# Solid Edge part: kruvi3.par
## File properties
Author: Mac
Template: Normal.par
Last saved by: Mac
Revision: 6
Application: Solid Edge
Material: Bronze, 90%
Face Style: Bronze
Fill Style: ANSI33(Brass)
Virtual Style: Brushed bronze
Coef. of Thermal Exp: 1.8e-05
Thermal Conductivity: 189.0
Specific Heat: 377.0
Modulus of Elasticity: 117210869000.0
Poission's Ratio: 0.36
Yield Stress: 372316878.0
Ultimate Stress: 420580177.0
Elongation: 0.0
Density: 8800,000 kg/m^3
Accuracy: 0,010
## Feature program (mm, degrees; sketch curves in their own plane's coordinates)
sketch for "unnamed Protrusion 1" plane through (0, 0, 0) normal (1, 0, 0) x-axis (0, 1, 0)
  circle centre (0.0026, 0) radius 0.3
extrude "unnamed Protrusion 1" add finite 2.3728 along -normal
lofted protrusion "unnamed LoftedProtrusion 1"
sketch for "unnamed Cutout 1" plane through (0.2791, 0.0026, 0) normal (1, 0, 0) x-axis (0, 1, 0)
  circle centre (0, 0) radius 0.366
extrude "unnamed Cutout 1" cut to key point along -normal
sketch for "ExtrudedCutout_2" plane through (-2.3728, 0.0026, 0) normal (-1, 0, 0) x-axis (0, -1, 0)
  circle centre (0, 0) radius 0.3547
extrude "ExtrudedCutout_2" cut finite 0.3354 along -normal
sketch for "unnamed Cutout 2" plane through (-2.0373, 0.0026, 0) normal (-1, 0, 0) x-axis (0, -1, 0)
  circle centre (0, 0) radius 0.2
extrude "unnamed Cutout 2" cut through along -normal
pattern "unnamed Pattern 1" of "unnamed LoftedProtrusion 1"
pattern "unnamed Pattern 2"
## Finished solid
Body 1: solid body, 19 faces, 48 edges, 30 vertices.
  Faces by surface: spline 12, plane 5, cylinder 2
  Edges by curve: intersection 18, circle 15, spline 12, curve on surface 3
Bounding box of the edges (mm; curved faces can reach further): 2.017 x 3.467 x 3.326, from (-2.0373, -1.9158, -1.4343) to (-0.0201, 1.5508, 1.8918).
Cylindrical faces by radius (mm): R0.2 x1, R0.3 x1
Planar faces by outward normal: +x 1, +z 1, -x 1, oblique 2
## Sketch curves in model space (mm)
arc centre (-1.648, 0.4619, 1.8918) radius 0.0014 from (-1.6467, 0.4624, 1.8918) through (-1.6476, 0.4606, 1.8918) to (-1.6494, 0.4616, 1.8918)
spline (-1.7756, 0.5603, 1.8918) -> (-1.7025, 0.5285, 1.8918) -> (-1.6494, 0.4616, 1.8918)
arc centre (-1.7756, 0.5616, 1.8918) radius 0.0013 from (-1.7756, 0.5629, 1.8918) through (-1.7769, 0.5615, 1.8918) to (-1.7756, 0.5603, 1.8918)
spline (-1.7756, 0.5629, 1.8918) -> (-1.7053, 0.5364, 1.8918) -> (-1.6467, 0.4624, 1.8918)
arc centre (-1.3822, -0.0313, 1.7526) radius 0.0125 from (-1.3941, -0.035, 1.7526) through (-1.3793, -0.0434, 1.7526) to (-1.3697, -0.0307, 1.7526)
spline (-1.8863, 0.6103, 1.7526) -> (-1.6125, 0.3469, 1.7526) -> (-1.3941, -0.035, 1.7526)
arc centre (-1.88, 0.6236, 1.7526) radius 0.0147 from (-1.87, 0.6343, 1.7526) through (-1.8926, 0.6311, 1.7526) to (-1.8863, 0.6103, 1.7526)
spline (-1.87, 0.6343, 1.7526) -> (-1.546, 0.34, 1.7526) -> (-1.3697, -0.0307, 1.7526)
arc centre (-0.7573, -0.5714, 1.2) radius 0.0237 from (-0.7356, -0.5618, 1.2) through (-0.7481, -0.5933, 1.2) to (-0.7782, -0.5827, 1.2)
spline (-2, 0.5574, 1.2) -> (-1.3412, 0.222, 1.2) -> (-0.7782, -0.5827, 1.2)
arc centre (-1.9952, 0.5785, 1.2) radius 0.0216 from (-1.9904, 0.5995, 1.2) through (-2.0164, 0.5826, 1.2) to (-2, 0.5574, 1.2)
spline (-1.9904, 0.5995, 1.2) -> (-1.2534, 0.2789, 1.2) -> (-0.7356, -0.5618, 1.2)
arc centre (-0.0072, -0.2062, 0) radius 0.0386 from (0, -0.244, 0) through (0.0314, -0.205, 0) to (0, -0.1683, 0)
spline (-2, 0.2493, 0) -> (-1.0025, 0.1403, 0) -> (0, -0.1683, 0)
arc centre (-1.9792, 0.2041, 0) radius 0.0498 from (-2, 0.2493, 0) through (-2.029, 0.2041, 0) to (-2, 0.1588, 0)
spline (-2, 0.1588, 0) -> (-1.1093, -0.1294, 0) -> (0, -0.244, 0)
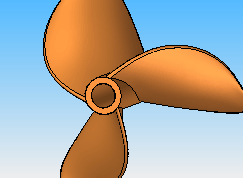
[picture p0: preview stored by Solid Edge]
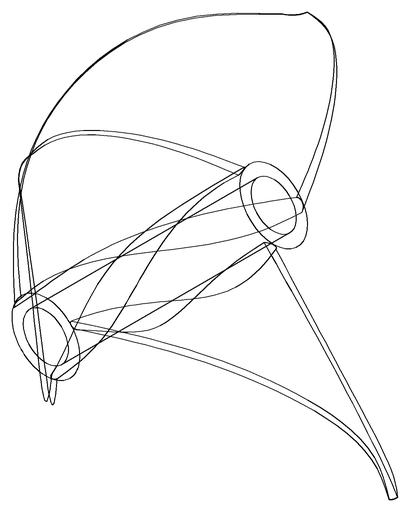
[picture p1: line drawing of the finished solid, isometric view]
